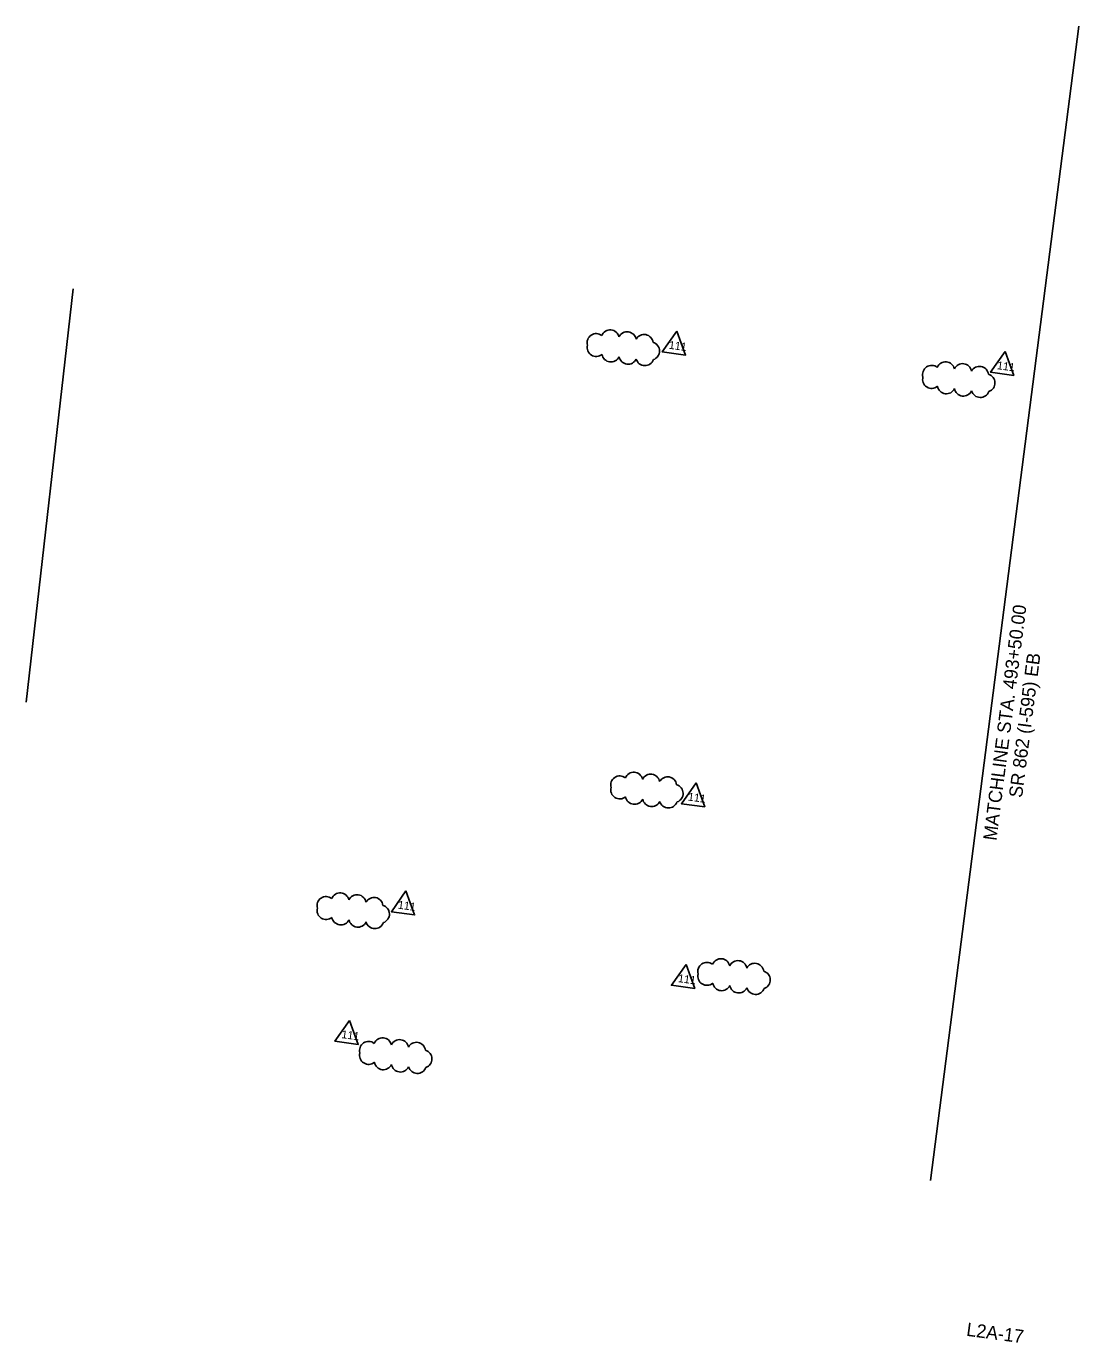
# Model space of a CAD drawing. Extents: x 926499 to 927786, y 636191 to 637140.
# Drawn here: x 927155 to 927786, y 636191 to 636981 of the extents above; entities that cross this region are included whole.
import ezdxf

# ---------------------------------------------------------------- set-up
doc = ezdxf.new("R2010")
doc.units = 0
for name, color, linetype in [('Cloud_dp', 7, 'Continuous'), ('MatchLines_dp', 7, 'Continuous'), ('TextShtNo', 7, 'Continuous')]:
    doc.layers.add(name, color=color, linetype=linetype)

msp = doc.modelspace()

# ---------------------------------------------------------------- linework, layer by layer
at = {"layer": 'Cloud_dp'}
for points in [[(927545.23, 636797.76), (927536.45, 636785.25), (927550.41, 636783.38)], [(927742.17, 636785.52), (927733.39, 636773.01), (927747.35, 636771.15)], [(927556.73, 636526.75), (927547.95, 636514.24), (927561.91, 636512.37)], [(927382.67, 636461.91), (927373.89, 636449.4), (927387.85, 636447.53)], [(927550.75, 636417.84), (927541.97, 636405.33), (927555.93, 636403.46)], [(927348.82, 636384.24), (927340.04, 636371.73), (927354, 636369.87)]]:
    msp.add_lwpolyline(points, close=True, dxfattribs=at)
for centre, start, end in [((927496.78, 636790.84), 51.51919, 196.51919), ((927505.16, 636793.02), 12.55842, 157.55842), ((927515.37, 636791.9), 9.95144, 154.95144), ((927525.5, 636790.29), 7.0359, 152.0359), ((927496.81, 636787.89), 164.87694, 309.87694), ((927529.38, 636785.75), 288.88829, 73.88829), ((927505.63, 636784.66), 189.88423, 334.88423), ((927515.88, 636783.29), 189.96243, 334.96243), ((927526.03, 636782.44), 195.45522, 340.45522), ((927706.43, 636773.9), 12.55842, 157.55842), ((927698.04, 636771.72), 51.51919, 196.51919), ((927716.63, 636772.78), 9.95144, 154.95144), ((927726.77, 636771.17), 7.0359, 152.0359), ((927730.65, 636766.63), 288.88829, 73.88829), ((927698.08, 636768.77), 164.87694, 309.87694), ((927706.9, 636765.54), 189.88423, 334.88423), ((927717.15, 636764.17), 189.96243, 334.96243), ((927727.29, 636763.32), 195.45522, 340.45522), ((927510.92, 636525.5), 51.51919, 196.51919), ((927519.31, 636527.68), 12.55842, 157.55842), ((927529.52, 636526.56), 9.95144, 154.95144), ((927539.65, 636524.95), 7.0359, 152.0359), ((927510.96, 636522.55), 164.87694, 309.87694), ((927543.53, 636520.41), 288.88829, 73.88829), ((927519.78, 636519.32), 189.88423, 334.88423), ((927530.03, 636517.95), 189.96243, 334.96243), ((927540.17, 636517.1), 195.45522, 340.45522), ((927334.72, 636453.14), 51.51919, 196.51919), ((927343.11, 636455.32), 12.55842, 157.55842), ((927353.32, 636454.2), 9.95144, 154.95144), ((927363.45, 636452.59), 7.0359, 152.0359), ((927334.76, 636450.19), 164.87694, 309.87694), ((927367.33, 636448.05), 288.88829, 73.88829), ((927343.58, 636446.96), 189.88423, 334.88423), ((927353.83, 636445.59), 189.96243, 334.96243), ((927363.97, 636444.74), 195.45522, 340.45522), ((927563.2, 636413.66), 51.51919, 196.51919), ((927571.59, 636415.83), 12.55842, 157.55842), ((927581.8, 636414.71), 9.95144, 154.95144), ((927591.93, 636413.11), 7.0359, 152.0359), ((927563.24, 636410.7), 164.87694, 309.87694), ((927595.81, 636408.57), 288.88829, 73.88829), ((927572.06, 636407.47), 189.88423, 334.88423), ((927582.31, 636406.11), 189.96243, 334.96243), ((927592.45, 636405.26), 195.45522, 340.45522), ((927360.21, 636366.24), 51.51919, 196.51919), ((927368.6, 636368.42), 12.55842, 157.55842), ((927378.81, 636367.3), 9.95144, 154.95144), ((927388.94, 636365.69), 7.0359, 152.0359), ((927360.25, 636363.29), 164.87694, 309.87694), ((927392.82, 636361.15), 288.88829, 73.88829), ((927369.07, 636360.06), 189.88423, 334.88423), ((927379.32, 636358.69), 189.96243, 334.96243), ((927389.46, 636357.84), 195.45522, 340.45522)]:
    msp.add_arc(centre, 5.42, start, end, dxfattribs=at)
at = {"layer": 'MatchLines_dp'}
for p, q in [((927786.29, 636980.55), (927697.3, 636288.29)), ((927154.86, 636575.07), (927182.89, 636823.15))]:
    msp.add_line(p, q, dxfattribs=at)

# ---------------------------------------------------------------- texts
at = {"layer": 'Cloud_dp'}
for p in [(927540.15, 636787.18), (927737.09, 636774.95), (927551.65, 636516.18), (927377.59, 636451.34), (927545.67, 636407.27), (927343.74, 636373.67)]:
    msp.add_text('111', height=4.8, rotation=352.38423, dxfattribs=at).set_placement(p)
at = {"layer": 'MatchLines_dp'}
for s, p in [('MATCHLINE STA. 493+50.00', (927736.88, 636491.81)), ('SR 862 (I-595) EB', (927752.28, 636517.48))]:
    msp.add_text(s, height=8, rotation=82.67462, dxfattribs=at).set_placement(p)
at = {"layer": 'TextShtNo'}
msp.add_text('L2A-17', height=8, rotation=352.38423, dxfattribs=at).set_placement((927718.57, 636195.1))

doc.saveas('drawing.dxf')
